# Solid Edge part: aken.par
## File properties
Author: Mac
Template: Normal.par
Last saved by: Mac
Revision: 3
Application: Solid Edge
Material: Aluminum, 1060
Face Style: Aluminum
Fill Style: ANSI38(Aluminum)
Virtual Style: Polished aluminum
Coef. of Thermal Exp: 2.3e-05
Thermal Conductivity: 221.0
Specific Heat: 920.0
Modulus of Elasticity: 68947570000.0
Poission's Ratio: 0.33
Yield Stress: 27579028.0
Ultimate Stress: 68947570.0
Elongation: 0.0
Density: 2712,000 kg/m^3
Accuracy: 0,990
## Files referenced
..\Asm17.asm
5C:\Documents and Settings\Mac\Desktop\paat6\Asm17.asm
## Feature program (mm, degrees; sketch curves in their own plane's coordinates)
sketch for "unnamed Protrusion 1" plane through (0, 0, 0) normal (0, 0, 1) x-axis (1, 0, 0)
  line (-4.427, 4.2739) -> (-4.427, -4.3261)
  arc centre (-4.227, -4.3261) radius 0.2 from (-4.227, -4.5261) to (-4.427, -4.3261) cw
  line (4.4988, -4.5261) -> (-4.227, -4.5261)
  arc centre (4.4988, -4.3261) radius 0.2 from (4.6988, -4.3261) to (4.4988, -4.5261) cw
  line (4.6988, -4.3261) -> (4.6988, 4.2739)
  arc centre (4.4988, 4.2739) radius 0.2 from (4.6988, 4.2739) to (4.4988, 4.4739) ccw
  line (4.4988, 4.4739) -> (-4.227, 4.4739)
  arc centre (-4.227, 4.2739) radius 0.2 from (-4.227, 4.4739) to (-4.427, 4.2739) ccw
extrude "unnamed Protrusion 1" add finite 0.4 along +normal
swept protrusion "SweptProtrusion_1"  CrossSections_Plane1_FractionOfCurve = 1
swept protrusion "SweptProtrusion_2"  CrossSections_Plane1_FractionOfCurve = 1
sketch for "ExtrudedProtrusion_2" plane through (0.1359, -0.0261, 0) normal (0, 0, -1) x-axis (1, 0, 0)
  line (-4.5629, -4.3) -> (-4.5629, 4.3)
  arc centre (-4.3629, 4.3) radius 0.2 from (-4.5629, 4.3) to (-4.3629, 4.5) cw
  line (-4.3629, 4.5) -> (4.3629, 4.5)
  arc centre (4.3629, 4.3) radius 0.2 from (4.3629, 4.5) to (4.5629, 4.3) cw
  line (4.5629, 4.3) -> (4.5629, -4.3)
  arc centre (4.3629, -4.3) radius 0.2 from (4.5629, -4.3) to (4.3629, -4.5) cw
  line (4.3629, -4.5) -> (-4.3629, -4.5)
  arc centre (-4.3629, -4.3) radius 0.2 from (-4.3629, -4.5) to (-4.5629, -4.3) cw
extrude "ExtrudedProtrusion_2" add finite 0.1 along +normal
sketch for "ExtrudedCutout_1" plane through (0.1359, -0.0261, -0.1) normal (0, 0, -1) x-axis (1, 0, 0)
  line (-4.5229, -4.3) -> (-4.5229, 4.3)
  arc centre (-4.3629, 4.3) radius 0.16 from (-4.5229, 4.3) to (-4.3629, 4.46) cw
  line (-4.3629, 4.46) -> (4.3629, 4.46)
  arc centre (4.3629, 4.3) radius 0.16 from (4.3629, 4.46) to (4.5229, 4.3) cw
  line (4.5229, 4.3) -> (4.5229, -4.3)
  arc centre (4.3629, -4.3) radius 0.16 from (4.5229, -4.3) to (4.3629, -4.46) cw
  line (4.3629, -4.46) -> (-4.3629, -4.46)
  arc centre (-4.3629, -4.3) radius 0.16 from (-4.3629, -4.46) to (-4.5229, -4.3) cw
extrude "ExtrudedCutout_1" cut finite 0.44 along -normal
sketch for "unnamed Cutout 1" plane through (0.1359, -0.0261, 0.4) normal (0, 0, 1) x-axis (1, 0, 0)
  circle centre (0, 0) radius 2
extrude "unnamed Cutout 1" cut through along -normal
sketch for "unnamed RevolvedProtrusion 1" plane through (0, -0.0261, 0) normal (0, -1, 0) x-axis (1, 0, 0)
  line (0.1359, 1.6) -> (1.0359, 1.6)
  arc centre (1.0359, 0.5) radius 1.1 from (2.1359, 0.5) to (1.0359, 1.6) ccw
  line (2.1359, 0.4) -> (2.1359, 0.5)
  line (2.1559, 0.4) -> (2.1359, 0.4)
  line (2.1559, 0.5) -> (2.1559, 0.4)
  arc centre (1.0359, 0.5) radius 1.12 from (1.0359, 1.62) to (2.1559, 0.5) cw
  line (0.1359, 1.62) -> (1.0359, 1.62)
revolve "unnamed RevolvedProtrusion 1" add finite 360 deg about sketch line (0.1359, 1.6) -> (0.1359, 1.62)
sketch for "unnamed Cutout 2" #1 plane through (0.1359, -0.0261, 1.62) normal (0, 0, 1) x-axis (1, 0, 0)
  arc centre (0, 0) radius 0.4485 from (0.3172, 0.3172) to (0.4485, 0) cw
  arc centre (0.4835, -0.0008) radius 0.035 from (0.4485, 0) to (0.5185, 0) ccw
  arc centre (0, 0) radius 0.5185 from (0.3667, 0.3667) to (0.5185, 0) cw
  arc centre (0.3419, 0.3419) radius 0.035 from (0.3667, 0.3667) to (0.3172, 0.3172) ccw
sketch for "unnamed Cutout 2" #2 plane through (0.1359, -0.0261, 1.62) normal (0, 0, 1) x-axis (1, 0, 0)
  arc centre (0, 0) radius 0.5885 from (0, 0.5885) to (0.4162, 0.4162) cw
  arc centre (0.4409, 0.4409) radius 0.035 from (0.4657, 0.4657) to (0.4162, 0.4162) cw
  arc centre (0, 0) radius 0.6585 from (0, 0.6585) to (0.4657, 0.4657) cw
  arc centre (0, 0.6235) radius 0.035 from (0, 0.6585) to (0, 0.5885) ccw
sketch for "unnamed Cutout 2" #3 plane through (0.1359, -0.0261, 1.62) normal (0, 0, 1) x-axis (1, 0, 0)
  arc centre (0, 0) radius 0.7285 from (0.5152, 0.5152) to (0.7285, 0) cw
  arc centre (0.7635, -0.0012) radius 0.035 from (0.7285, 0) to (0.7985, 0) ccw
  arc centre (0, 0) radius 0.7985 from (0.5647, 0.5647) to (0.7985, 0) cw
  arc centre (0.5399, 0.5399) radius 0.035 from (0.5152, 0.5152) to (0.5647, 0.5647) cw
sketch for "unnamed Cutout 2" #4 plane through (0.1359, -0.0261, 1.62) normal (0, 0, 1) x-axis (1, 0, 0)
  arc centre (0, 0) radius 0.4485 from (0.3172, -0.3172) to (0, -0.4485) cw
  arc centre (-0.0008, -0.4835) radius 0.035 from (0, -0.4485) to (0, -0.5185) ccw
  arc centre (0, 0) radius 0.5185 from (0.3667, -0.3667) to (0, -0.5185) cw
  arc centre (0.3419, -0.3419) radius 0.035 from (0.3667, -0.3667) to (0.3172, -0.3172) ccw
sketch for "unnamed Cutout 2" #5 plane through (0.1359, -0.0261, 1.62) normal (0, 0, 1) x-axis (1, 0, 0)
  arc centre (0, 0) radius 0.5885 from (0.5885, 0) to (0.4162, -0.4162) cw
  arc centre (0.4409, -0.4409) radius 0.035 from (0.4657, -0.4657) to (0.4162, -0.4162) cw
  arc centre (0, 0) radius 0.6585 from (0.6585, 0) to (0.4657, -0.4657) cw
  arc centre (0.6235, 0) radius 0.035 from (0.6585, 0) to (0.5885, 0) ccw
sketch for "unnamed Cutout 2" #6 plane through (0.1359, -0.0261, 1.62) normal (0, 0, 1) x-axis (1, 0, 0)
  arc centre (0, 0) radius 0.7285 from (0.5152, -0.5152) to (0, -0.7285) cw
  arc centre (-0.0012, -0.7635) radius 0.035 from (0, -0.7285) to (0, -0.7985) ccw
  arc centre (0, 0) radius 0.7985 from (0.5647, -0.5647) to (0, -0.7985) cw
  arc centre (0.5399, -0.5399) radius 0.035 from (0.5152, -0.5152) to (0.5647, -0.5647) cw
sketch for "unnamed Cutout 2" #7 plane through (0.1359, -0.0261, 1.62) normal (0, 0, 1) x-axis (1, 0, 0)
  arc centre (0, 0) radius 0.4485 from (-0.3172, -0.3172) to (-0.4485, 0) cw
  arc centre (-0.4835, 0.0008) radius 0.035 from (-0.4485, 0) to (-0.5185, 0) ccw
  arc centre (0, 0) radius 0.5185 from (-0.3667, -0.3667) to (-0.5185, 0) cw
  arc centre (-0.3419, -0.3419) radius 0.035 from (-0.3667, -0.3667) to (-0.3172, -0.3172) ccw
sketch for "unnamed Cutout 2" #8 plane through (0.1359, -0.0261, 1.62) normal (0, 0, 1) x-axis (1, 0, 0)
  arc centre (0, 0) radius 0.5885 from (0, -0.5885) to (-0.4162, -0.4162) cw
  arc centre (-0.4409, -0.4409) radius 0.035 from (-0.4657, -0.4657) to (-0.4162, -0.4162) cw
  arc centre (0, 0) radius 0.6585 from (0, -0.6585) to (-0.4657, -0.4657) cw
  arc centre (0, -0.6235) radius 0.035 from (0, -0.6585) to (0, -0.5885) ccw
sketch for "unnamed Cutout 2" #9 plane through (0.1359, -0.0261, 1.62) normal (0, 0, 1) x-axis (1, 0, 0)
  arc centre (0, 0) radius 0.7285 from (-0.5152, -0.5152) to (-0.7285, 0) cw
  arc centre (-0.7635, 0.0012) radius 0.035 from (-0.7285, 0) to (-0.7985, 0) ccw
  arc centre (0, 0) radius 0.7985 from (-0.5647, -0.5647) to (-0.7985, 0) cw
  arc centre (-0.5399, -0.5399) radius 0.035 from (-0.5152, -0.5152) to (-0.5647, -0.5647) cw
sketch for "unnamed Cutout 2" #10 plane through (0.1359, -0.0261, 1.62) normal (0, 0, 1) x-axis (1, 0, 0)
  arc centre (0, 0) radius 0.4485 from (-0.3172, 0.3172) to (0, 0.4485) cw
  arc centre (0.0008, 0.4835) radius 0.035 from (0, 0.4485) to (0, 0.5185) ccw
  arc centre (0, 0) radius 0.5185 from (-0.3667, 0.3667) to (0, 0.5185) cw
  arc centre (-0.3419, 0.3419) radius 0.035 from (-0.3667, 0.3667) to (-0.3172, 0.3172) ccw
sketch for "unnamed Cutout 2" #11 plane through (0.1359, -0.0261, 1.62) normal (0, 0, 1) x-axis (1, 0, 0)
  arc centre (0, 0) radius 0.5885 from (-0.5885, 0) to (-0.4162, 0.4162) cw
  arc centre (-0.4409, 0.4409) radius 0.035 from (-0.4657, 0.4657) to (-0.4162, 0.4162) cw
  arc centre (0, 0) radius 0.6585 from (-0.6585, 0) to (-0.4657, 0.4657) cw
  arc centre (-0.6235, 0) radius 0.035 from (-0.6585, 0) to (-0.5885, 0) ccw
sketch for "unnamed Cutout 2" #12 plane through (0.1359, -0.0261, 1.62) normal (0, 0, 1) x-axis (1, 0, 0)
  arc centre (0, 0) radius 0.7285 from (-0.5152, 0.5152) to (0, 0.7285) cw
  arc centre (0.0012, 0.7635) radius 0.035 from (0, 0.7285) to (0, 0.7985) ccw
  arc centre (0, 0) radius 0.7985 from (-0.5647, 0.5647) to (0, 0.7985) cw
  arc centre (-0.5399, 0.5399) radius 0.035 from (-0.5152, 0.5152) to (-0.5647, 0.5647) cw
extrude "unnamed Cutout 2" cut through along -normal
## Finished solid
Body 1: solid body, 90 faces, 238 edges, 152 vertices.
  Faces by surface: cylinder 62, plane 18, torus 6, cone 4
  Edges by curve: circle 138, line 100
Bounding box of the edges (mm; curved faces can reach further): 10.017 x 9.891 x 1.720, from (-4.8727, -4.9718, -0.1) to (5.1444, 4.9196, 1.62).
Cylindrical faces by radius (mm): R0.0177 x4, R0.035 x24, R0.16 x4, R0.2 x4, R0.4485 x4, R0.5185 x4, R0.5885 x4, R0.6585 x4, R0.7285 x4, R0.7985 x4, R2 x1, R2.02 x1
Conical faces (half-angle, radius in mm at the cone's reference point): 50 deg R0.2 x2, 50 deg R0.6394 x2
Toroidal faces (ring radius, tube radius in mm): R0.628 r0.0177 x4, R0.9 r1.1 x1, R0.9 r1.12 x1
Planar faces by outward normal: +x 2, +y 2, +z 2, -x 2, -y 2, -z 4, oblique 4
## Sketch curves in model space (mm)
arc centre (-4.227, -4.3261, 0) radius 0.2 from (-4.227, -4.5261, 0) through (-4.3725, -4.4633, 0) to (-4.427, -4.3261, 0)
line (4.4988, -4.5261, 0) -> (-4.227, -4.5261, 0)
arc centre (4.4988, -4.3261, 0) radius 0.2 from (4.6988, -4.3261, 0) through (4.636, -4.4715, 0) to (4.4988, -4.5261, 0)
line (4.6988, -4.3261, 0) -> (4.6988, 4.2739, 0)
arc centre (4.4988, 4.2739, 0) radius 0.2 from (4.6988, 4.2739, 0) through (4.636, 4.4194, 0) to (4.4988, 4.4739, 0)
line (4.4988, 4.4739, 0) -> (-4.227, 4.4739, 0)
arc centre (-4.227, 4.2739, 0) radius 0.2 from (-4.227, 4.4739, 0) through (-4.3725, 4.4112, 0) to (-4.427, 4.2739, 0)
line (-4.427, 4.2739, 0) -> (-4.427, -4.3261, 0)
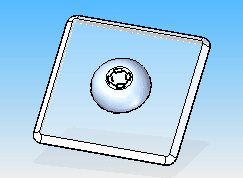
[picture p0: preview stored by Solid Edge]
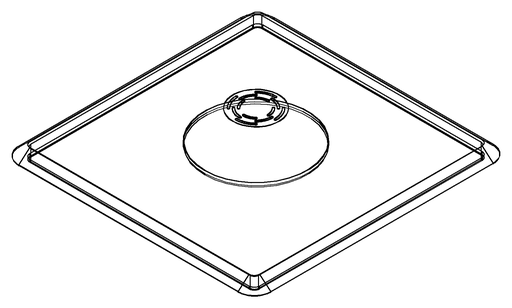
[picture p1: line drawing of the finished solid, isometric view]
